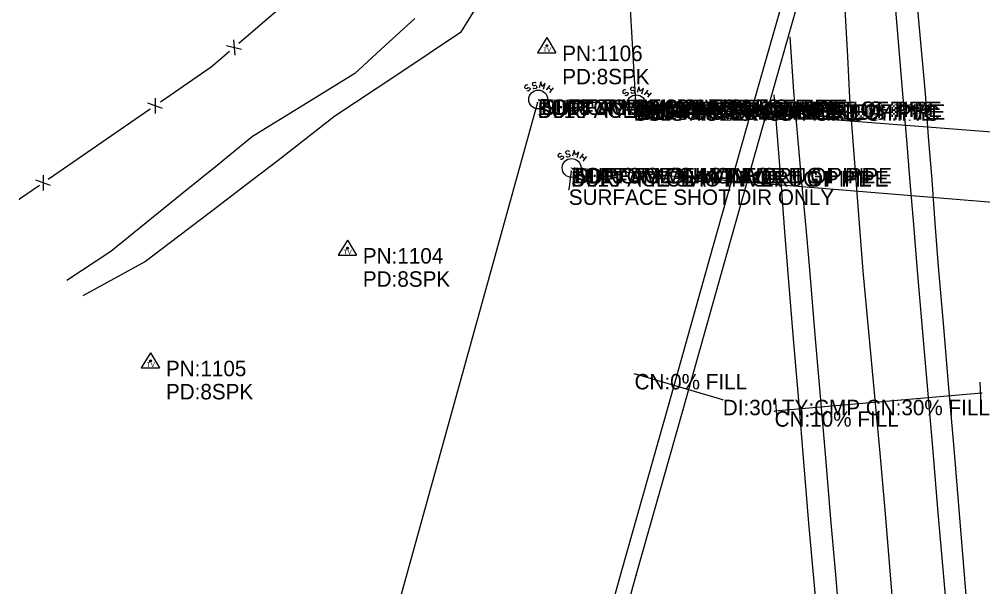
# Model space of a CAD drawing. Extents: x 929765 to 934279, y 1533086 to 1541189.
# Drawn here: x 931751.4 to 932063, y 1537135.2 to 1537318.7 of the extents above; entities that cross this region are included whole.
import ezdxf

# ---------------------------------------------------------------- set-up
doc = ezdxf.new("R2010")
doc.units = 0
for name, color, linetype in [('S_CROSS_DRAIN', 7, 'Continuous'), ('S_CROSS_DRAIN_ANNOT', 7, 'Continuous'), ('S_DITCHLINE', 7, 'Continuous'), ('S_DRG_PT_SYM', 7, 'Continuous'), ('S_EDGE_PAVEMENT', 7, 'Continuous'), ('S_FENCE', 7, 'Continuous'), ('S_HEADWALL', 7, 'Continuous'), ('S_MANHOLE_ANNOT', 7, 'Continuous'), ('S_MSC_PT_SYM', 7, 'Continuous'), ('S_PAVEMENT_CROWN', 7, 'Continuous'), ('S_RAILROAD', 7, 'Continuous'), ('S_SANITARY_SEWER', 7, 'Continuous'), ('S_SANITARY_SEWER_ANNOT', 7, 'Continuous'), ('S_SECONDARY_CTL', 7, 'Continuous'), ('S_SECONDARY_CTL_ANNOT', 7, 'Continuous'), ('S_SHOULDER', 7, 'Continuous'), ('S_SURVEY_TEXT_ANNOT', 7, 'Continuous'), ('S_UTL_PT_SYM', 7, 'Continuous')]:
    doc.layers.add(name, color=color, linetype=linetype)

msp = doc.modelspace()

# ---------------------------------------------------------------- linework, layer by layer
at = {"layer": 'S_CROSS_DRAIN'}
for p, q in [((931978.95, 1537195.64), (931950.4, 1537203.99)), ((932062.71, 1537197.8), (931995.7, 1537191.94))]:
    msp.add_line(p, q, dxfattribs=at)
at = {"layer": 'S_DITCHLINE'}
for points in [[(931964.13, 1537470.78), (931958.69, 1537458.85), (931953.25, 1537446.93), (931956.11, 1537425.64), (931962.3, 1537423.93), (931964.69, 1537424.11), (931966.9, 1537401.27), (931969.1, 1537378.44), (931958.88, 1537373.67), (931949.96, 1537376.9), (931937.32, 1537372.75), (931924.68, 1537368.59), (931916.88, 1537353.63), (931909.08, 1537338.66), (931901.6, 1537326.5), (931894.11, 1537314.34), (931873.82, 1537300.85), (931853.53, 1537287.36), (931835.12, 1537272.97), (931824.41, 1537264.81), (931813.7, 1537256.65), (931802.99, 1537248.49), (931792.29, 1537240.33), (931772.04, 1537229.23)], [(931879.34, 1537318.94), (931869.65, 1537310.02), (931859.97, 1537301.1), (931843.4, 1537290.91), (931826.83, 1537280.71), (931815.38, 1537271.41), (931803.92, 1537262.12), (931792.47, 1537252.82), (931781.02, 1537243.53), (931766.83, 1537234.17)]]:
    msp.add_lwpolyline(points, dxfattribs=at)
at = {"layer": 'S_DRG_PT_SYM'}
for points in [[(931950.4, 1537203.99), (931950.4, 1537204.04), (931950.4, 1537203.99), (931950.35, 1537203.99), (931950.4, 1537203.99), (931950.4, 1537203.94), (931950.4, 1537203.99), (931950.45, 1537203.99)], [(932062.71, 1537197.8), (932062.71, 1537197.85), (932062.71, 1537197.8), (932062.66, 1537197.8), (932062.71, 1537197.8), (932062.71, 1537197.75), (932062.71, 1537197.8), (932062.76, 1537197.8)], [(931978.95, 1537195.64), (931978.95, 1537195.69), (931978.95, 1537195.64), (931978.9, 1537195.64), (931978.95, 1537195.64), (931978.95, 1537195.59), (931978.95, 1537195.64), (931979, 1537195.64)], [(931995.7, 1537191.94), (931995.7, 1537191.99), (931995.7, 1537191.94), (931995.65, 1537191.94), (931995.7, 1537191.94), (931995.7, 1537191.89), (931995.7, 1537191.94), (931995.75, 1537191.94)]]:
    msp.add_lwpolyline(points, dxfattribs=at)
at = {"layer": 'S_EDGE_PAVEMENT'}
for points in [[(932059.21, 1537034.36), (932058.05, 1537048.52), (932056.89, 1537062.69), (932055.72, 1537076.85), (932054.56, 1537091.01), (932053.08, 1537108.03), (932051.6, 1537125.05), (932050.12, 1537142.07), (932048.64, 1537159.08), (932046.94, 1537178.95), (932045.24, 1537198.83), (932043.54, 1537218.7), (932041.84, 1537238.57), (932040.71, 1537252.26), (932039.58, 1537265.94), (932038.44, 1537279.63), (932037.31, 1537293.31), (932035.21, 1537317.83), (932033.1, 1537342.36), (932031.84, 1537358.72), (932030.59, 1537375.09), (932029.34, 1537391.46), (932028.08, 1537407.83)], [(932024.4, 1537036.12), (932023.24, 1537049.63), (932022.08, 1537063.14), (932020.92, 1537076.65), (932019.76, 1537090.16), (932018.3, 1537106.87), (932016.84, 1537123.59), (932015.38, 1537140.3), (932013.92, 1537157.01), (932012.23, 1537176.89), (932010.54, 1537196.76), (932008.86, 1537216.64), (932007.17, 1537236.51), (932005.86, 1537251.22), (932004.55, 1537265.93), (932003.24, 1537280.64), (932001.93, 1537295.34), (932000.68, 1537312.96)]]:
    msp.add_lwpolyline(points, dxfattribs=at)
at = {"layer": 'S_FENCE'}
for p, q in [((931820.67, 1537311.98), (931821.16, 1537307.01)), ((931820.67, 1537311.98), (931821.16, 1537307.01)), ((931823.34, 1537308.87), (931818.49, 1537310.12)), ((931823.34, 1537308.87), (931818.49, 1537310.12)), ((931795.43, 1537293.2), (931795.38, 1537288.2)), ((931795.43, 1537293.2), (931795.38, 1537288.2)), ((931797.75, 1537289.82), (931793.06, 1537291.57)), ((931797.75, 1537289.82), (931793.06, 1537291.57)), ((931759.18, 1537268.27), (931759.13, 1537263.27)), ((931759.18, 1537268.27), (931759.13, 1537263.27)), ((931761.5, 1537264.89), (931756.81, 1537266.64)), ((931761.5, 1537264.89), (931756.81, 1537266.64))]:
    msp.add_line(p, q, dxfattribs=at)
for points in [[(931837.62, 1537323.81), (931822.43, 1537310.8)], [(931837.62, 1537323.81), (931822.43, 1537310.8)], [(931819.4, 1537308.19), (931813.53, 1537303.17)], [(931819.4, 1537308.19), (931813.53, 1537303.17)], [(931813.53, 1537303.17), (931797.05, 1537291.83)], [(931813.53, 1537303.17), (931797.05, 1537291.83)], [(931793.76, 1537289.57), (931760.8, 1537266.9)], [(931793.76, 1537289.57), (931760.8, 1537266.9)], [(931757.97, 1537264.95), (931751.48, 1537260.49)], [(931757.97, 1537264.95), (931751.48, 1537260.49)]]:
    msp.add_lwpolyline(points, dxfattribs=at)
at = {"layer": 'S_HEADWALL'}
for points in [[(932062.12, 1537201.3), (932062.39, 1537193.55)], [(931996.65, 1537188.15), (931996.01, 1537196.07)]]:
    msp.add_lwpolyline(points, dxfattribs=at)
at = {"layer": 'S_MSC_PT_SYM'}
for points in [[(931813.53, 1537303.17), (931813.53, 1537303.22), (931813.53, 1537303.17), (931813.48, 1537303.17), (931813.53, 1537303.17), (931813.53, 1537303.12), (931813.53, 1537303.17), (931813.58, 1537303.17)], [(931920.24, 1537292.7), (931920.24, 1537292.75), (931920.24, 1537292.7), (931920.19, 1537292.7), (931920.24, 1537292.7), (931920.24, 1537292.65), (931920.24, 1537292.7), (931920.29, 1537292.7)], [(931989.67, 1537294.03), (931989.67, 1537294.08), (931989.67, 1537294.03), (931989.62, 1537294.03), (931989.67, 1537294.03), (931989.67, 1537293.98), (931989.67, 1537294.03), (931989.72, 1537294.03)], [(931994.39, 1537292.75), (931994.39, 1537292.8), (931994.39, 1537292.75), (931994.34, 1537292.75), (931994.39, 1537292.75), (931994.39, 1537292.7), (931994.39, 1537292.75), (931994.44, 1537292.75)], [(931919.02, 1537291.78), (931919.02, 1537291.83), (931919.02, 1537291.78), (931918.97, 1537291.78), (931919.02, 1537291.78), (931919.02, 1537291.73), (931919.02, 1537291.78), (931919.07, 1537291.78)], [(931950.09, 1537290.85), (931950.09, 1537290.9), (931950.09, 1537290.85), (931950.04, 1537290.85), (931950.09, 1537290.85), (931950.09, 1537290.8), (931950.09, 1537290.85), (931950.14, 1537290.85)], [(931950.77, 1537292.06), (931950.77, 1537292.11), (931950.77, 1537292.06), (931950.72, 1537292.06), (931950.77, 1537292.06), (931950.77, 1537292.01), (931950.77, 1537292.06), (931950.82, 1537292.06)], [(931951.89, 1537291.15), (931951.89, 1537291.2), (931951.89, 1537291.15), (931951.84, 1537291.15), (931951.89, 1537291.15), (931951.89, 1537291.1), (931951.89, 1537291.15), (931951.94, 1537291.15)], [(931930.95, 1537270.6), (931930.95, 1537270.65), (931930.95, 1537270.6), (931930.9, 1537270.6), (931930.95, 1537270.6), (931930.95, 1537270.55), (931930.95, 1537270.6), (931931, 1537270.6)], [(931929.86, 1537269.58), (931929.86, 1537269.63), (931929.86, 1537269.58), (931929.81, 1537269.58), (931929.86, 1537269.58), (931929.86, 1537269.53), (931929.86, 1537269.58), (931929.91, 1537269.58)], [(931751.48, 1537260.49), (931751.48, 1537260.54), (931751.48, 1537260.49), (931751.43, 1537260.49), (931751.48, 1537260.49), (931751.48, 1537260.44), (931751.48, 1537260.49), (931751.53, 1537260.49)], [(931975.7, 1537244.87), (931975.7, 1537244.92), (931975.7, 1537244.87), (931975.65, 1537244.87), (931975.7, 1537244.87), (931975.7, 1537244.82), (931975.7, 1537244.87), (931975.75, 1537244.87)], [(931980.45, 1537243.48), (931980.45, 1537243.53), (931980.45, 1537243.48), (931980.4, 1537243.48), (931980.45, 1537243.48), (931980.45, 1537243.43), (931980.45, 1537243.48), (931980.5, 1537243.48)], [(931961.44, 1537194.14), (931961.44, 1537194.19), (931961.44, 1537194.14), (931961.39, 1537194.14), (931961.44, 1537194.14), (931961.44, 1537194.09), (931961.44, 1537194.14), (931961.49, 1537194.14)], [(931966.1, 1537192.51), (931966.1, 1537192.56), (931966.1, 1537192.51), (931966.05, 1537192.51), (931966.1, 1537192.51), (931966.1, 1537192.46), (931966.1, 1537192.51), (931966.15, 1537192.51)], [(931946.32, 1537140.45), (931946.32, 1537140.5), (931946.32, 1537140.45), (931946.27, 1537140.45), (931946.32, 1537140.45), (931946.32, 1537140.4), (931946.32, 1537140.45), (931946.37, 1537140.45)], [(931950.98, 1537138.91), (931950.98, 1537138.96), (931950.98, 1537138.91), (931950.93, 1537138.91), (931950.98, 1537138.91), (931950.98, 1537138.86), (931950.98, 1537138.91), (931951.03, 1537138.91)]]:
    msp.add_lwpolyline(points, dxfattribs=at)
at = {"layer": 'S_PAVEMENT_CROWN'}
msp.add_lwpolyline([(932041.76, 1537037.1), (932040.61, 1537050.43), (932039.45, 1537063.77), (932038.3, 1537077.1), (932037.14, 1537090.44), (932035.75, 1537107.51), (932034.36, 1537124.59), (932032.97, 1537141.66), (932031.58, 1537158.74), (932029.79, 1537178.36), (932027.99, 1537197.98), (932026.19, 1537217.6), (932024.39, 1537237.22), (932023.31, 1537251.24), (932022.23, 1537265.26), (932021.15, 1537279.28), (932020.07, 1537293.3), (932019.35, 1537306.62), (932018.64, 1537319.95), (932017.92, 1537333.27), (932017.2, 1537346.6), (932015.42, 1537361.67)], dxfattribs=at)
at = {"layer": 'S_RAILROAD'}
for p, q in [((931989.67, 1537294.03), (932000.29, 1537331.57)), ((931994.39, 1537292.75), (932005.02, 1537330.1)), ((931975.7, 1537244.87), (931989.67, 1537294.03)), ((931980.45, 1537243.48), (931994.39, 1537292.75)), ((931961.44, 1537194.14), (931975.7, 1537244.87)), ((931966.1, 1537192.51), (931980.45, 1537243.48)), ((931946.32, 1537140.45), (931961.44, 1537194.14)), ((931950.98, 1537138.91), (931966.1, 1537192.51)), ((931931.04, 1537086.37), (931946.32, 1537140.45)), ((931935.87, 1537085.13), (931950.98, 1537138.91))]:
    msp.add_line(p, q, dxfattribs=at)
at = {"layer": 'S_SANITARY_SEWER'}
for p, q in [((931950.77, 1537292.06), (931940.09, 1537483.33)), ((931914.92, 1537297.03), (931914.85, 1537296.64)), ((931914.85, 1537296.64), (931915.04, 1537296.37)), ((931915.47, 1537297.41), (931914.92, 1537297.03)), ((931915.04, 1537296.37), (931915.47, 1537296.25)), ((931915.89, 1537297.34), (931915.47, 1537297.41)), ((931915.47, 1537296.25), (931916.01, 1537296.6)), ((931916.01, 1537295.44), (931915.62, 1537295.51)), ((931916.01, 1537296.6), (931916.47, 1537296.52)), ((931916.55, 1537295.82), (931916.01, 1537295.44)), ((931916.47, 1537296.52), (931916.63, 1537296.25)), ((931916.63, 1537296.25), (931916.55, 1537295.82)), ((931921.9, 1537295.79), (931923.14, 1537297.26)), ((931922.56, 1537296.56), (931923.53, 1537295.75)), ((931924.11, 1537296.44), (931922.87, 1537294.97)), ((931947.19, 1537295.86), (931946.64, 1537295.47)), ((931947.61, 1537295.78), (931947.19, 1537295.86)), ((931953.62, 1537294.23), (931954.86, 1537295.7)), ((931950.09, 1537290.85), (931920.24, 1537292.7)), ((931946.64, 1537295.47), (931946.57, 1537295.08)), ((931946.57, 1537295.08), (931946.76, 1537294.81)), ((931946.76, 1537294.81), (931947.19, 1537294.7)), ((931947.19, 1537294.7), (931947.73, 1537295.04)), ((931947.73, 1537293.88), (931947.34, 1537293.96)), ((931947.73, 1537295.04), (931948.19, 1537294.97)), ((931948.27, 1537294.27), (931947.73, 1537293.88)), ((931948.19, 1537294.97), (931948.35, 1537294.7)), ((931948.35, 1537294.7), (931948.27, 1537294.27)), ((931954.28, 1537295.01), (931955.25, 1537294.19)), ((931955.83, 1537294.89), (931954.59, 1537293.42)), ((931919.02, 1537291.78), (931833.98, 1536985.2)), ((931951.89, 1537291.15), (932168.84, 1537274.16)), ((931925.73, 1537274.88), (931925.65, 1537274.49)), ((931925.65, 1537274.49), (931925.84, 1537274.22)), ((931926.27, 1537275.27), (931925.73, 1537274.88)), ((931925.84, 1537274.22), (931926.27, 1537274.11)), ((931926.7, 1537275.19), (931926.27, 1537275.27)), ((931926.27, 1537274.11), (931926.81, 1537274.46)), ((931926.81, 1537274.46), (931927.28, 1537274.38)), ((931927.35, 1537273.68), (931926.81, 1537273.29)), ((931927.28, 1537274.38), (931927.43, 1537274.11)), ((931927.43, 1537274.11), (931927.35, 1537273.68)), ((931932.7, 1537273.64), (931933.94, 1537275.11)), ((931933.36, 1537274.42), (931934.33, 1537273.6)), ((931934.91, 1537274.3), (931933.67, 1537272.83)), ((931926.81, 1537273.29), (931926.42, 1537273.37)), ((931930.95, 1537270.6), (932152.35, 1537252.49)), ((931929.86, 1537269.58), (931929.14, 1537263.64))]:
    msp.add_line(p, q, dxfattribs=at)
for points in [[(931918.57, 1537297.96), (931918.22, 1537298.23), (931917.56, 1537298.15), (931917.33, 1537297.8), (931917.37, 1537297.49), (931917.71, 1537297.18), (931918.33, 1537297.3), (931918.72, 1537296.99), (931918.76, 1537296.68), (931918.49, 1537296.29), (931917.87, 1537296.21), (931917.52, 1537296.48)], [(931921.01, 1537296.1), (931921.55, 1537297.96), (931920.5, 1537296.95), (931920.12, 1537298.38), (931919.57, 1537296.52)], [(931950.29, 1537296.4), (931949.94, 1537296.67), (931949.28, 1537296.59), (931949.05, 1537296.25), (931949.08, 1537295.94), (931949.43, 1537295.63), (931950.05, 1537295.74), (931950.44, 1537295.43), (931950.48, 1537295.12), (931950.21, 1537294.73), (931949.59, 1537294.66), (931949.24, 1537294.93)], [(931952.73, 1537294.54), (931953.27, 1537296.4), (931952.22, 1537295.39), (931951.84, 1537296.83), (931951.29, 1537294.97)], [(931929.37, 1537275.81), (931929.02, 1537276.08), (931928.36, 1537276.01), (931928.13, 1537275.66), (931928.17, 1537275.35), (931928.52, 1537275.04), (931929.14, 1537275.15), (931929.52, 1537274.84), (931929.56, 1537274.53), (931929.29, 1537274.15), (931928.67, 1537274.07), (931928.32, 1537274.34)], [(931931.81, 1537273.95), (931932.35, 1537275.81), (931931.31, 1537274.8), (931930.92, 1537276.24), (931930.38, 1537274.38)]]:
    msp.add_lwpolyline(points, dxfattribs=at)
for centre in [(931919.25, 1537292.72), (931950.97, 1537291.17), (931930.05, 1537270.58)]:
    msp.add_circle(centre, 3.05, dxfattribs=at)
at = {"layer": 'S_SECONDARY_CTL'}
for p, q in [((931922.01, 1537312.74), (931919, 1537307.79)), ((931922.01, 1537312.74), (931924.96, 1537307.79)), ((931919, 1537307.79), (931924.96, 1537307.79)), ((931857.54, 1537247.29), (931854.53, 1537242.34)), ((931857.54, 1537247.29), (931860.48, 1537242.34)), ((931854.53, 1537242.34), (931860.48, 1537242.34)), ((931793.85, 1537210.87), (931790.84, 1537205.92)), ((931793.85, 1537210.87), (931796.8, 1537205.92)), ((931790.84, 1537205.92), (931796.8, 1537205.92))]:
    msp.add_line(p, q, dxfattribs=at)
for centre, radius in [((931922.01, 1537310.13), 0.311), ((931922.01, 1537310.13), 0.183), ((931922.01, 1537310.13), 0.103), ((931857.54, 1537244.68), 0.311), ((931857.54, 1537244.68), 0.183), ((931857.54, 1537244.68), 0.103), ((931793.85, 1537208.26), 0.311), ((931793.85, 1537208.26), 0.183), ((931793.85, 1537208.26), 0.103)]:
    msp.add_circle(centre, radius, dxfattribs=at)
at = {"layer": 'S_SHOULDER'}
for points in [[(932065.34, 1537035.86), (932064.27, 1537049.8), (932063.21, 1537063.74), (932062.14, 1537077.68), (932061.08, 1537091.63), (932059.66, 1537108.77), (932058.23, 1537125.91), (932056.81, 1537143.06), (932055.39, 1537160.2), (932053.73, 1537179.84), (932052.07, 1537199.48), (932050.41, 1537219.11), (932048.75, 1537238.75), (932047.67, 1537252.72), (932046.6, 1537266.7), (932045.52, 1537280.67), (932044.45, 1537294.64), (932042.28, 1537319.47), (932040.11, 1537344.3), (932038.43, 1537365.02), (932036.75, 1537385.74), (932035.07, 1537406.47), (932033.39, 1537427.19)], [(932017.74, 1537036.33), (932016.51, 1537049.59), (932015.29, 1537062.86), (932014.07, 1537076.12), (932012.85, 1537089.38), (932011.34, 1537105.97), (932009.83, 1537122.57), (932008.33, 1537139.16), (932006.82, 1537155.75), (932005.16, 1537175.6), (932003.5, 1537195.45), (932001.85, 1537215.3), (932000.19, 1537235.14), (931999.04, 1537249.92), (931997.89, 1537264.69), (931996.74, 1537279.47), (931995.59, 1537294.25)]]:
    msp.add_lwpolyline(points, dxfattribs=at)
at = {"layer": 'S_UTL_PT_SYM'}
for points in [[(931919.25, 1537292.72), (931919.25, 1537292.77), (931919.25, 1537292.72), (931919.2, 1537292.72), (931919.25, 1537292.72), (931919.25, 1537292.67), (931919.25, 1537292.72), (931919.3, 1537292.72)], [(931920.24, 1537292.7), (931920.24, 1537292.75), (931920.24, 1537292.7), (931920.19, 1537292.7), (931920.24, 1537292.7), (931920.24, 1537292.65), (931920.24, 1537292.7), (931920.29, 1537292.7)], [(931919.02, 1537291.78), (931919.02, 1537291.83), (931919.02, 1537291.78), (931918.97, 1537291.78), (931919.02, 1537291.78), (931919.02, 1537291.73), (931919.02, 1537291.78), (931919.07, 1537291.78)], [(931950.09, 1537290.85), (931950.09, 1537290.9), (931950.09, 1537290.85), (931950.04, 1537290.85), (931950.09, 1537290.85), (931950.09, 1537290.8), (931950.09, 1537290.85), (931950.14, 1537290.85)], [(931950.77, 1537292.06), (931950.77, 1537292.11), (931950.77, 1537292.06), (931950.72, 1537292.06), (931950.77, 1537292.06), (931950.77, 1537292.01), (931950.77, 1537292.06), (931950.82, 1537292.06)], [(931950.97, 1537291.17), (931950.97, 1537291.22), (931950.97, 1537291.17), (931950.92, 1537291.17), (931950.97, 1537291.17), (931950.97, 1537291.12), (931950.97, 1537291.17), (931951.02, 1537291.17)], [(931951.89, 1537291.15), (931951.89, 1537291.2), (931951.89, 1537291.15), (931951.84, 1537291.15), (931951.89, 1537291.15), (931951.89, 1537291.1), (931951.89, 1537291.15), (931951.94, 1537291.15)], [(931930.05, 1537270.58), (931930.05, 1537270.63), (931930.05, 1537270.58), (931930, 1537270.58), (931930.05, 1537270.58), (931930.05, 1537270.53), (931930.05, 1537270.58), (931930.1, 1537270.58)], [(931930.95, 1537270.6), (931930.95, 1537270.65), (931930.95, 1537270.6), (931930.9, 1537270.6), (931930.95, 1537270.6), (931930.95, 1537270.55), (931930.95, 1537270.6), (931931, 1537270.6)], [(931929.86, 1537269.58), (931929.86, 1537269.63), (931929.86, 1537269.58), (931929.81, 1537269.58), (931929.86, 1537269.58), (931929.86, 1537269.53), (931929.86, 1537269.58), (931929.91, 1537269.58)], [(931929.14, 1537263.64), (931929.14, 1537263.69), (931929.14, 1537263.64), (931929.09, 1537263.64), (931929.14, 1537263.64), (931929.14, 1537263.59), (931929.14, 1537263.64), (931929.19, 1537263.64)]]:
    msp.add_lwpolyline(points, dxfattribs=at)

# ---------------------------------------------------------------- texts
at = {"layer": 'S_CROSS_DRAIN_ANNOT'}
for s, p in [('CN:0% FILL', (931950.4, 1537198.99)), ("DI:30' TY:CMP CN:30% FILL LN:30", (931978.95, 1537190.64)), ('CN:10% FILL', (931995.7, 1537186.94))]:
    msp.add_text(s, height=5, dxfattribs=at).set_placement(p)
at = {"layer": 'S_MANHOLE_ANNOT'}
for p in [(931919.25, 1537287.72), (931950.97, 1537286.17), (931930.05, 1537265.58)]:
    msp.add_text('BOTTOM OF MANHOLE', height=5, dxfattribs=at).set_placement(p)
at = {"layer": 'S_SANITARY_SEWER_ANNOT'}
for s, p in [('TOP OF MANHOLE', (931919.25, 1537287.72)), ('DI:18" TY:PVC INVERT OF PIPE', (931920.24, 1537287.7)), ('DI:18" TY:PVC INVERT OF PIPE', (931919.02, 1537286.78)), ('DI:18" INVERT OF PIPE TY:PVC', (931950.09, 1537285.85)), ('TOP OF MANHOLE', (931950.97, 1537286.17)), ('DI:12" TY:PVC INVERT OF PIPE', (931950.77, 1537287.06)), ('DI:18" TY:PVC INVERT OF PIPE', (931951.89, 1537286.15)), ('TOP OF MANHOLE', (931930.05, 1537265.58)), ('DI:15" TY:CLAY INVERT OF PIPE', (931930.95, 1537265.6)), ('DI:15" TY:CLAY INVERT OF PIPE', (931929.86, 1537264.58)), ('SURFACE SHOT DIR ONLY', (931929.14, 1537258.64))]:
    msp.add_text(s, height=5, dxfattribs=at).set_placement(p)
at = {"layer": 'S_SECONDARY_CTL'}
for p in [(931920.81, 1537308.12), (931856.33, 1537242.67), (931792.64, 1537206.25)]:
    msp.add_text('TV', height=1.5, rotation=360, dxfattribs=at).set_placement(p)
at = {"layer": 'S_SECONDARY_CTL_ANNOT'}
for s, p in [('PN:1106', (931927.01, 1537305.13)), ('PD:8SPK', (931927.01, 1537297.63)), ('PN:1104', (931862.54, 1537239.68)), ('PD:8SPK', (931862.54, 1537232.18)), ('PN:1105', (931798.85, 1537203.26)), ('PD:8SPK', (931798.85, 1537195.76))]:
    msp.add_text(s, height=5, dxfattribs=at).set_placement(p)
at = {"layer": 'S_SURVEY_TEXT_ANNOT'}
for p in [(931920.24, 1537287.7), (931919.02, 1537286.78), (931950.09, 1537285.85), (931950.77, 1537287.06), (931951.89, 1537286.15), (931930.95, 1537265.6), (931929.86, 1537264.58)]:
    msp.add_text('SURFACE SHOT FOR UG PIPE', height=5, dxfattribs=at).set_placement(p)

doc.saveas('drawing.dxf')
